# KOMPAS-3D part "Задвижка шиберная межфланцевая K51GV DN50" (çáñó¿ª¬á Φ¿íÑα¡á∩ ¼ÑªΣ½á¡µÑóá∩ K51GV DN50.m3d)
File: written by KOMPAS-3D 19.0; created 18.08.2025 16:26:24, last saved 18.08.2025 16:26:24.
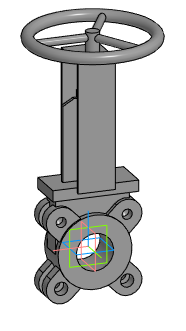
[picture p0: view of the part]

Document properties: Автор: Евгений; Полное имя файла: E:\Dendor Работа Сачек\3D для проектировщиков\2.4 Тип K51GV. Задвижка шиберная межфланцевая\stp_Задвижка шиберная K51GV DN50-400 с маховиком\Задвижка шиберная межфланцевая K51GV DN50.m3d

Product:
- Part/product: Задвижка шиберная межфланцевая K51GV DN50

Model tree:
1. Операция без истории:1  (labels: Задвижка шиберная межфланцевая K51GV DN50)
